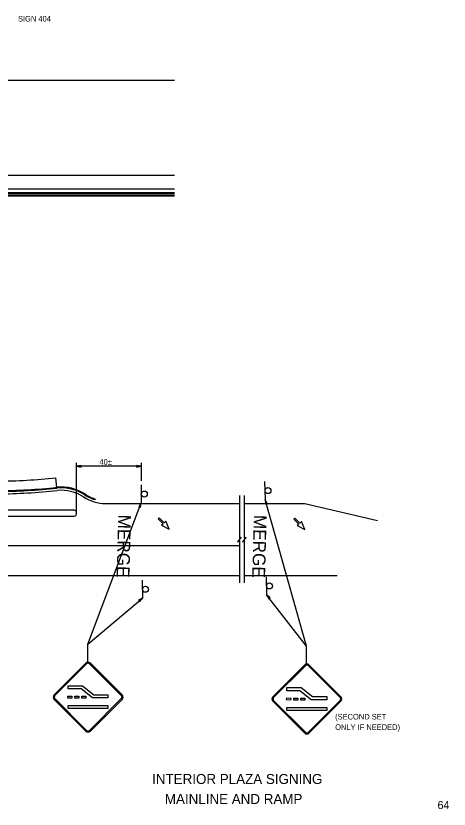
# Model space of a CAD drawing. Extents: x 524708 to 525491, y 1531861 to 1532506.
# Drawn here: x 525219.9 to 525490.6, y 1531873.5 to 1532368.8 of the extents above; entities that cross this region are included whole.
import ezdxf

# ---------------------------------------------------------------- set-up
doc = ezdxf.new("R2010")
doc.units = 0
for name, color, linetype in [('Guardrail', 7, 'Continuous'), ('LeaderLine_dp', 7, 'Continuous'), ('PavtMessage', 7, 'Continuous'), ('PMMisc', 7, 'Continuous'), ('RoadwayMisc', 7, 'Continuous'), ('SignPanel', 7, 'Continuous'), ('SignSupport', 7, 'Continuous'), ('TextLabel', 7, 'Continuous'), ('TextMisc', 7, 'Continuous'), ('TextShtNo', 7, 'Continuous')]:
    doc.layers.add(name, color=color, linetype=linetype)

msp = doc.modelspace()

# ---------------------------------------------------------------- linework, layer by layer
at = {"layer": 'Guardrail'}
msp.add_line((525195.73, 1532256.47), (525319.12, 1532256.47), dxfattribs=at)
at = {"layer": 'LeaderLine_dp'}
for p, q in [((525257.88, 1532058.34), (525257.88, 1532089.72)), ((525260.78, 1532088.15), (525257.88, 1532087.61)), ((525298.22, 1532087.55), (525257.88, 1532087.61)), ((525257.88, 1532087.61), (525260.77, 1532087.05)), ((525260.56, 1532087.61), (525260.78, 1532088.15)), ((525260.77, 1532087.05), (525260.56, 1532087.61)), ((525298.22, 1532087.55), (525295.32, 1532088.11)), ((525295.32, 1532088.11), (525295.54, 1532087.55)), ((525295.54, 1532087.55), (525295.32, 1532087.01)), ((525295.32, 1532087.01), (525298.22, 1532087.55)), ((525298.22, 1532089.72), (525298.22, 1532078.49)), ((525375.68, 1532066.88), (525375.93, 1532063.94)), ((525376.99, 1532064.24), (525375.68, 1532066.88)), ((525401.55, 1531975.3), (525375.68, 1532066.88)), ((525264.9, 1531976.46), (525298.25, 1532064.77)), ((525298.25, 1532064.77), (525296.7, 1532062.26)), ((525296.7, 1532062.26), (525297.3, 1532062.27)), ((525297.3, 1532062.27), (525297.73, 1532061.87)), ((525297.73, 1532061.87), (525298.25, 1532064.77)), ((525375.93, 1532063.94), (525376.41, 1532064.3)), ((525376.41, 1532064.3), (525376.99, 1532064.24)), ((525401.55, 1531975.3), (525376.58, 1532007.37)), ((525376.58, 1532007.37), (525377.92, 1532004.74)), ((525378.79, 1532005.41), (525376.58, 1532007.37)), ((525264.9, 1531976.46), (525299.14, 1532005.26)), ((525299.14, 1532005.26), (525296.56, 1532003.82)), ((525296.56, 1532003.82), (525297.09, 1532003.53)), ((525297.09, 1532003.53), (525297.27, 1532002.98)), ((525297.27, 1532002.98), (525299.14, 1532005.26)), ((525377.92, 1532004.74), (525378.22, 1532005.25)), ((525378.22, 1532005.25), (525378.79, 1532005.41)), ((525264.93, 1531965.07), (525264.9, 1531976.46)), ((525401.58, 1531963.91), (525401.55, 1531975.3))]:
    msp.add_line(p, q, dxfattribs=at)
at = {"layer": 'PavtMessage'}
for p, q in [((525309.52, 1532055.42), (525308.91, 1532054.84)), ((525308.91, 1532054.84), (525312.01, 1532051.58)), ((525312.62, 1532052.15), (525309.52, 1532055.42)), ((525312.01, 1532051.58), (525310.88, 1532050.71)), ((525313.54, 1532053.24), (525312.62, 1532052.15)), ((525315.76, 1532048.24), (525313.54, 1532053.24)), ((525394.26, 1532055.21), (525393.65, 1532054.64)), ((525393.65, 1532054.64), (525396.75, 1532051.38)), ((525397.36, 1532051.95), (525394.26, 1532055.21)), ((525396.75, 1532051.38), (525395.62, 1532050.51)), ((525398.28, 1532053.03), (525397.36, 1532051.95)), ((525400.5, 1532048.04), (525398.28, 1532053.03)), ((525310.88, 1532050.71), (525315.76, 1532048.24)), ((525395.62, 1532050.51), (525400.5, 1532048.04))]:
    msp.add_line(p, q, dxfattribs=at)
at = {"layer": 'PMMisc'}
msp.add_line((525208.71, 1532038.01), (525359.59, 1532038.01), dxfattribs=at)
at = {"layer": 'RoadwayMisc'}
for p, q in [((524930.4, 1532328.73), (525319.12, 1532328.73)), ((525028.44, 1532269.28), (525319.12, 1532269.28)), ((525195.73, 1532260.74), (525319.12, 1532260.74)), ((525195.73, 1532258.6), (525319.12, 1532258.6)), ((525195.73, 1532258.07), (525319.12, 1532258.07)), ((525195.73, 1532257), (525319.12, 1532257)), ((525245.5, 1532074.38), (525244.86, 1532080.35)), ((525359.59, 1532069.37), (525359.59, 1532042.68)), ((525362.63, 1532069.37), (525362.63, 1532042.68)), ((525275.97, 1532064.24), (525359.59, 1532064.24)), ((525362.63, 1532064.24), (525400.5, 1532064.24)), ((525400.5, 1532064.24), (525445.88, 1532053.81)), ((525213.89, 1532060.32), (525255.89, 1532060.32)), ((525213.89, 1532056.32), (525255.89, 1532056.32)), ((525360.75, 1532043.2), (525358.44, 1532040.47)), ((525359.59, 1532042.68), (525360.75, 1532043.2)), ((525363.79, 1532043.2), (525361.47, 1532040.47)), ((525362.63, 1532042.68), (525363.79, 1532043.2)), ((525358.44, 1532040.47), (525359.59, 1532041.31)), ((525359.59, 1532041.31), (525359.59, 1532014.83)), ((525361.47, 1532040.47), (525362.63, 1532041.31)), ((525362.63, 1532041.31), (525362.63, 1532014.83)), ((525108.71, 1532019.32), (525359.59, 1532019.32)), ((525362.63, 1532019.32), (525420.63, 1532019.32))]:
    msp.add_line(p, q, dxfattribs=at)
for centre, radius, start, end in [((525207.22, 1532428.57), 350.25, 270.2388, 276.1694), ((525207.22, 1532428.6), 356.25, 270.2375, 276.1752), ((525207.22, 1532428.6), 356.75, 270.2375, 276.1752), ((525207.22, 1532428.6), 358.25, 270.2375, 276.1752), ((525248.44, 1532047.58), 27, 56.4357, 96.1704), ((525248.44, 1532047.58), 26.5, 56.4357, 96.1704), ((525248.44, 1532047.58), 25, 56.4357, 96.1704), ((525276.09, 1532089.24), 25, 236.4357, 269.7206), ((525276.09, 1532089.24), 23.5, 236.4357, 253.0681), ((525276.09, 1532089.24), 23, 236.4357, 254.5578), ((525255.89, 1532058.32), 2, 269.9999, 90.0236)]:
    msp.add_arc(centre, radius, start, end, dxfattribs=at)
at = {"layer": 'SignPanel'}
for p, q in [((525243.85, 1531944.85), (525263.65, 1531964.64)), ((525244.32, 1531944.37), (525264.12, 1531964.17)), ((525266, 1531964.17), (525285.8, 1531944.37)), ((525266.48, 1531964.64), (525286.28, 1531944.85)), ((525380.5, 1531943.68), (525400.3, 1531963.48)), ((525380.97, 1531943.21), (525400.77, 1531963.01)), ((525402.65, 1531963.01), (525422.45, 1531943.21)), ((525403.13, 1531963.48), (525422.92, 1531943.68)), ((525252.63, 1531950.51), (525261.5, 1531950.51)), ((525252.63, 1531948.57), (525252.63, 1531950.51)), ((525260.67, 1531948.57), (525252.63, 1531948.57)), ((525267.75, 1531942.95), (525260.67, 1531948.57)), ((525261.5, 1531950.51), (525268.59, 1531944.89)), ((525389.28, 1531949.35), (525398.15, 1531949.35)), ((525389.28, 1531947.41), (525389.28, 1531949.35)), ((525397.32, 1531947.41), (525389.28, 1531947.41)), ((525404.4, 1531941.78), (525397.32, 1531947.41)), ((525398.15, 1531949.35), (525405.24, 1531943.72)), ((525264.12, 1531922.69), (525244.32, 1531942.49)), ((525252.45, 1531942.8), (525252.46, 1531944.05)), ((525254.95, 1531942.78), (525252.45, 1531942.8)), ((525252.46, 1531944.05), (525254.96, 1531944.03)), ((525254.96, 1531944.03), (525254.95, 1531942.78)), ((525256.83, 1531942.77), (525256.84, 1531944.02)), ((525259.33, 1531942.75), (525256.83, 1531942.77)), ((525256.84, 1531944.02), (525259.34, 1531944)), ((525259.34, 1531944), (525259.33, 1531942.75)), ((525261.2, 1531942.73), (525261.21, 1531943.98)), ((525263.7, 1531942.71), (525261.2, 1531942.73)), ((525261.21, 1531943.98), (525263.71, 1531943.96)), ((525263.71, 1531943.96), (525263.7, 1531942.71)), ((525285.8, 1531942.49), (525266, 1531922.69)), ((525277.46, 1531942.95), (525267.75, 1531942.95)), ((525268.59, 1531944.89), (525277.46, 1531944.89)), ((525277.46, 1531944.89), (525277.46, 1531942.95)), ((525389.1, 1531941.64), (525389.11, 1531942.89)), ((525389.11, 1531942.89), (525391.61, 1531942.87)), ((525391.61, 1531942.87), (525391.6, 1531941.62)), ((525393.48, 1531941.6), (525393.49, 1531942.85)), ((525393.49, 1531942.85), (525395.99, 1531942.83)), ((525395.99, 1531942.83), (525395.98, 1531941.58)), ((525397.85, 1531941.57), (525397.86, 1531942.82)), ((525397.86, 1531942.82), (525400.36, 1531942.8)), ((525400.36, 1531942.8), (525400.35, 1531941.55)), ((525405.24, 1531943.72), (525414.11, 1531943.72)), ((525414.11, 1531943.72), (525414.11, 1531941.78)), ((525263.65, 1531922.22), (525243.85, 1531942.02)), ((525252.63, 1531938.12), (525277.46, 1531938.12)), ((525252.63, 1531936.35), (525252.63, 1531938.12)), ((525286.28, 1531942.02), (525266.48, 1531922.22)), ((525277.46, 1531938.12), (525277.46, 1531936.35)), ((525400.3, 1531921.05), (525380.5, 1531940.85)), ((525400.77, 1531921.53), (525380.97, 1531941.33)), ((525391.6, 1531941.62), (525389.1, 1531941.64)), ((525395.98, 1531941.58), (525393.48, 1531941.6)), ((525400.35, 1531941.55), (525397.85, 1531941.57)), ((525422.45, 1531941.33), (525402.65, 1531921.53)), ((525422.92, 1531940.85), (525403.13, 1531921.05)), ((525414.11, 1531941.78), (525404.4, 1531941.78)), ((525277.46, 1531936.35), (525252.63, 1531936.35)), ((525389.28, 1531936.96), (525414.11, 1531936.96)), ((525389.28, 1531935.18), (525389.28, 1531936.96)), ((525414.11, 1531935.18), (525389.28, 1531935.18)), ((525414.11, 1531936.96), (525414.11, 1531935.18))]:
    msp.add_line(p, q, dxfattribs=at)
for centre, radius, start, end in [((525265.06, 1531963.23), 2, 45, 135), ((525265.06, 1531963.23), 1.33, 45, 135), ((525401.71, 1531962.07), 2, 45, 135), ((525401.71, 1531962.07), 1.33, 45, 135), ((525245.26, 1531943.43), 2, 135, 225), ((525245.26, 1531943.43), 1.33, 135, 225), ((525284.86, 1531943.43), 1.33, 315, 45), ((525284.86, 1531943.43), 2, 315, 45), ((525381.91, 1531942.27), 2, 135, 225), ((525381.91, 1531942.27), 1.33, 135, 225), ((525421.51, 1531942.27), 1.33, 315, 45), ((525421.51, 1531942.27), 2, 315, 45), ((525265.06, 1531923.63), 1.33, 225, 315), ((525265.06, 1531923.63), 2, 225, 315), ((525401.71, 1531922.47), 2, 225, 315), ((525401.71, 1531922.47), 1.33, 225, 315)]:
    msp.add_arc(centre, radius, start, end, dxfattribs=at)
at = {"layer": 'SignSupport'}
for p, q in [((525298.22, 1532076.03), (525298.25, 1532064.77)), ((525375.31, 1532078.13), (525375.68, 1532066.88)), ((525376.21, 1532018.61), (525376.58, 1532007.37)), ((525298.77, 1532016.5), (525299.14, 1532005.26))]:
    msp.add_line(p, q, dxfattribs=at)
for centre in [(525300.17, 1532070.2), (525377.44, 1532072.36), (525300.9, 1532010.74), (525378.34, 1532012.85)]:
    msp.add_circle(centre, 1.87, dxfattribs=at)

# ---------------------------------------------------------------- texts
at = {"layer": 'PavtMessage'}
for p in [(525283.9, 1532057.47), (525368.64, 1532057.27)]:
    msp.add_text('MERGE', height=7.999, rotation=268.4419, dxfattribs=at).set_placement(p)
at = {"layer": 'TextLabel'}
for s, p in [('SIGN 404', (525221.26, 1532365.23)), ('40±', (525272.13, 1532088.54)), ('(SECOND SET', (525419.37, 1531929.47)), ('ONLY IF NEEDED)', (525419.37, 1531922.97))]:
    msp.add_text(s, height=3.5, dxfattribs=at).set_placement(p)
at = {"layer": 'TextMisc'}
for s, p in [(' INTERIOR PLAZA SIGNING ', (525302.75, 1531889.2)), ('   MAINLINE AND RAMP    ', (525306.05, 1531876.7))]:
    msp.add_text(s, height=6.25, rotation=360, dxfattribs=at).set_placement(p)
at = {"layer": 'TextShtNo'}
msp.add_text('64', height=5, rotation=360, dxfattribs=at).set_placement((525483.36, 1531873.57))

doc.saveas('drawing.dxf')
